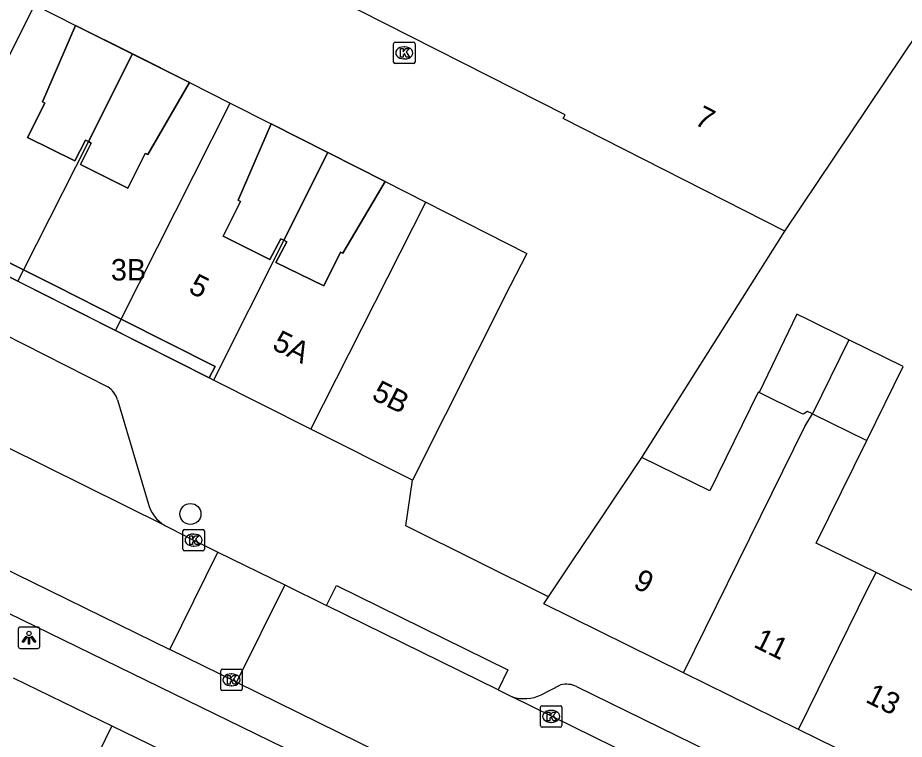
# Model space of a CAD drawing. Extents: x 160356 to 161355, y 381727 to 382845.
# Drawn here: x 160776.6 to 160817.89, y 382478.89 to 382512.49 of the extents above; entities that cross this region are included whole.
import ezdxf

# ---------------------------------------------------------------- set-up
doc = ezdxf.new("R2010")
doc.units = 0
for name, color, linetype in [('IMGEO_Boom', 7, 'Continuous'), ('IMGEO_Kolk', 7, 'Continuous'), ('IMGEO_Lichtpunt', 7, 'Continuous'), ('IMGEO_Pand', 7, 'Continuous'), ('IMGEO_Pand_nummerreeks', 7, 'Continuous'), ('IMGEO_Pand_overbouw', 7, 'Continuous'), ('IMGEO_Rijbaan_lokaal_open', 7, 'Continuous'), ('IMGEO_Voetpad_open', 7, 'Continuous')]:
    doc.layers.add(name, color=color, linetype=linetype)

msp = doc.modelspace()

# ---------------------------------------------------------------- linework, layer by layer
at = {"layer": 'IMGEO_Boom'}
msp.add_circle((160784.641, 382489.379), 0.489, dxfattribs=at)
at = {"layer": 'IMGEO_Kolk'}
for p, q in [((160794.176, 382511.356), (160795.028, 382511.356)), ((160794.101, 382510.43), (160794.101, 382511.282)), ((160794.589, 382511.136), (160794.614, 382511.136)), ((160795.102, 382511.282), (160795.102, 382510.43)), ((160794.612, 382510.576), (160794.587, 382510.576)), ((160795.028, 382510.356), (160794.176, 382510.356)), ((160784.288, 382487.735), (160784.288, 382488.587)), ((160784.363, 382488.661), (160785.215, 382488.661)), ((160785.289, 382488.587), (160785.289, 382487.735)), ((160784.776, 382488.441), (160784.801, 382488.441)), ((160784.799, 382487.881), (160784.774, 382487.881)), ((160785.215, 382487.661), (160784.363, 382487.661)), ((160786.053, 382481.227), (160786.053, 382482.079)), ((160786.128, 382482.153), (160786.98, 382482.153)), ((160787.054, 382482.079), (160787.054, 382481.227)), ((160786.541, 382481.933), (160786.566, 382481.933)), ((160786.98, 382481.153), (160786.128, 382481.153)), ((160786.564, 382481.373), (160786.539, 382481.373)), ((160800.941, 382479.524), (160800.941, 382480.376)), ((160801.016, 382480.45), (160801.868, 382480.45)), ((160801.942, 382480.376), (160801.942, 382479.524)), ((160801.429, 382480.23), (160801.454, 382480.23)), ((160801.452, 382479.67), (160801.427, 382479.67)), ((160801.868, 382479.45), (160801.016, 382479.45))]:
    msp.add_line(p, q, dxfattribs=at)
for points in [[(160794.176, 382511.356), (160795.028, 382511.356)], [(160794.101, 382510.43), (160794.101, 382511.282)], [(160794.422, 382511.056), (160794.545, 382511.056), (160794.545, 382510.905), (160794.675, 382511.056), (160794.839, 382511.056), (160794.693, 382510.905), (160794.846, 382510.656), (160794.694, 382510.656), (160794.609, 382510.82), (160794.545, 382510.753), (160794.545, 382510.656), (160794.422, 382510.656), (160794.422, 382511.056)], [(160795.102, 382511.282), (160795.102, 382510.43)], [(160795.028, 382510.356), (160794.176, 382510.356)], [(160784.288, 382487.735), (160784.288, 382488.587)], [(160784.363, 382488.661), (160785.215, 382488.661)], [(160785.289, 382488.587), (160785.289, 382487.735)], [(160784.609, 382488.361), (160784.732, 382488.361), (160784.732, 382488.21), (160784.862, 382488.361), (160785.026, 382488.361), (160784.88, 382488.21), (160785.033, 382487.961), (160784.881, 382487.961), (160784.796, 382488.125), (160784.732, 382488.058), (160784.732, 382487.961), (160784.609, 382487.961), (160784.609, 382488.361)], [(160785.215, 382487.661), (160784.363, 382487.661)], [(160786.053, 382481.227), (160786.053, 382482.079)], [(160786.128, 382482.153), (160786.98, 382482.153)], [(160787.054, 382482.079), (160787.054, 382481.227)], [(160786.374, 382481.853), (160786.497, 382481.853), (160786.497, 382481.702), (160786.627, 382481.853), (160786.791, 382481.853), (160786.645, 382481.702), (160786.798, 382481.453), (160786.646, 382481.453), (160786.561, 382481.617), (160786.497, 382481.55), (160786.497, 382481.453), (160786.374, 382481.453), (160786.374, 382481.853)], [(160786.98, 382481.153), (160786.128, 382481.153)], [(160800.941, 382479.524), (160800.941, 382480.376)], [(160801.016, 382480.45), (160801.868, 382480.45)], [(160801.942, 382480.376), (160801.942, 382479.524)], [(160801.262, 382480.15), (160801.385, 382480.15), (160801.385, 382479.999), (160801.515, 382480.15), (160801.679, 382480.15), (160801.533, 382479.999), (160801.686, 382479.75), (160801.534, 382479.75), (160801.449, 382479.914), (160801.385, 382479.847), (160801.385, 382479.75), (160801.262, 382479.75), (160801.262, 382480.15)], [(160801.868, 382479.45), (160801.016, 382479.45)]]:
    msp.add_lwpolyline(points, dxfattribs=at)
for centre, start, end in [((160794.178, 382511.28), 91.552, 178.448), ((160794.178, 382511.28), 91.552, 178.448), ((160795.026, 382511.28), 1.552, 88.448), ((160795.026, 382511.28), 1.552, 88.448), ((160794.178, 382510.432), 181.552, 268.448), ((160794.178, 382510.432), 181.552, 268.448), ((160795.026, 382510.432), 271.552, 358.448), ((160795.026, 382510.432), 271.552, 358.448), ((160784.365, 382488.585), 91.552, 178.448), ((160784.365, 382488.585), 91.552, 178.448), ((160785.213, 382488.585), 1.552, 88.448), ((160785.213, 382488.585), 1.552, 88.448), ((160784.365, 382487.737), 181.552, 268.448), ((160784.365, 382487.737), 181.552, 268.448), ((160785.213, 382487.737), 271.552, 358.448), ((160785.213, 382487.737), 271.552, 358.448), ((160786.13, 382482.077), 91.552, 178.448), ((160786.13, 382482.077), 91.552, 178.448), ((160786.978, 382482.077), 1.552, 88.448), ((160786.978, 382482.077), 1.552, 88.448), ((160786.13, 382481.229), 181.552, 268.448), ((160786.13, 382481.229), 181.552, 268.448), ((160786.978, 382481.229), 271.552, 358.448), ((160786.978, 382481.229), 271.552, 358.448), ((160801.018, 382480.374), 91.552, 178.448), ((160801.018, 382480.374), 91.552, 178.448), ((160801.866, 382480.374), 1.552, 88.448), ((160801.866, 382480.374), 1.552, 88.448), ((160801.018, 382479.526), 181.552, 268.448), ((160801.018, 382479.526), 181.552, 268.448), ((160801.866, 382479.526), 271.552, 358.448), ((160801.866, 382479.526), 271.552, 358.448)]:
    msp.add_arc(centre, 0.0765, start, end, dxfattribs=at)
for centre, major_axis, ratio, start_param, end_param in [((160794.588, 382510.856), (-0.387, 0.002), 0.722429, 4.712389, 7.853982), ((160794.613, 382510.856), (-0.39, 0.002), 0.717154, 1.570796, 4.712389), ((160784.775, 382488.161), (-0.387, 0.002), 0.722429, 4.712389, 7.853982), ((160784.8, 382488.161), (-0.39, 0.002), 0.717154, 1.570796, 4.712389), ((160786.54, 382481.653), (-0.387, 0.002), 0.722429, 4.712389, 7.853982), ((160786.565, 382481.653), (-0.39, 0.002), 0.717154, 1.570796, 4.712389), ((160801.428, 382479.95), (-0.387, 0.002), 0.722429, 4.712389, 7.853982), ((160801.453, 382479.95), (-0.39, 0.002), 0.717154, 1.570796, 4.712389)]:
    msp.add_ellipse(centre, major_axis=major_axis, ratio=ratio, start_param=start_param, end_param=end_param, dxfattribs=at)
at = {"layer": 'IMGEO_Lichtpunt'}
for p, q in [((160777.526, 382484.114), (160776.718, 382484.114)), ((160777.526, 382484.114), (160776.718, 382484.114)), ((160776.624, 382484.019), (160776.624, 382483.212)), ((160776.624, 382484.019), (160776.624, 382483.212)), ((160777.62, 382483.212), (160777.62, 382484.019)), ((160777.62, 382483.212), (160777.62, 382484.019)), ((160776.718, 382483.118), (160777.526, 382483.118)), ((160776.718, 382483.118), (160777.526, 382483.118))]:
    msp.add_line(p, q, dxfattribs=at)
for points in [[(160776.998, 382483.683), (160777.037, 382483.655), (160776.849, 382483.393), (160776.811, 382483.42), (160776.998, 382483.683)], [(160777.1, 382483.635), (160777.147, 382483.635), (160777.147, 382483.313), (160777.1, 382483.313), (160777.1, 382483.635)], [(160777.21, 382483.655), (160777.248, 382483.682), (160777.435, 382483.42), (160777.396, 382483.392), (160777.21, 382483.655)]]:
    msp.add_lwpolyline(points, dxfattribs=at)
msp.add_circle((160777.123, 382483.817), 0.0994, dxfattribs=at)
for centre, start, end in [((160776.718, 382484.019), 90, 180), ((160776.718, 382484.019), 90, 180), ((160777.526, 382484.019), 0, 90), ((160777.526, 382484.019), 0, 90), ((160776.718, 382483.212), 180, 270), ((160776.718, 382483.212), 180, 270), ((160777.526, 382483.212), 270, 0), ((160777.526, 382483.212), 270, 360)]:
    msp.add_arc(centre, 0.0946, start, end, dxfattribs=at)
at = {"layer": 'IMGEO_Pand'}
for points in [[(160812.331, 382502.558), (160820.876, 382515.321), (160798.417, 382527.033), (160799.163, 382528.464), (160793.416, 382531.651)], [(160812.331, 382502.558), (160802.004, 382507.798), (160802.09, 382507.968), (160791.3, 382513.443), (160794.82, 382520.017), (160794.601, 382520.138), (160795.088, 382521.018), (160784.777, 382526.556), (160784.711, 382526.444), (160784.461, 382526.591)], [(160772.322, 382503.039), (160777.393, 382513.097)], [(160777.393, 382513.097), (160779.292, 382512.135)], [(160779.887, 382506.727), (160779.753, 382506.797), (160779.251, 382505.823), (160777.057, 382506.918), (160777.86, 382508.514), (160777.749, 382508.58), (160779.292, 382512.135)], [(160784.593, 382509.477), (160782.656, 382506.125), (160782.534, 382506.17), (160781.729, 382504.559), (160779.528, 382505.659), (160780.021, 382506.658), (160779.887, 382506.727)], [(160784.593, 382509.477), (160786.493, 382508.512)], [(160781.422, 382498.451), (160786.493, 382508.512)], [(160786.493, 382508.512), (160788.394, 382507.546)], [(160788.991, 382502.131), (160788.856, 382502.201), (160788.343, 382501.233), (160786.164, 382502.326), (160786.975, 382503.929), (160786.859, 382503.991), (160788.394, 382507.546)], [(160779.887, 382506.727), (160776.871, 382500.745)], [(160793.704, 382504.866), (160791.741, 382501.533), (160791.631, 382501.578), (160790.846, 382500), (160788.623, 382501.087), (160789.126, 382502.062), (160788.991, 382502.131)], [(160793.704, 382504.866), (160795.61, 382503.899)], [(160790.249, 382493.331), (160795.61, 382503.899)], [(160795.61, 382503.899), (160800.303, 382501.518), (160799.539, 382500), (160794.983, 382490.948)], [(160772.322, 382503.039), (160776.871, 382500.745)], [(160788.991, 382502.131), (160785.711, 382495.616)], [(160776.871, 382500.745), (160778.35, 382500), (160781.422, 382498.451)], [(160815.3, 382497.497), (160813.329, 382498.468), (160812.978, 382498.64), (160812.88, 382498.688), (160811.124, 382495.03)], [(160781.422, 382498.451), (160785.79, 382496.249), (160785.515, 382495.715)], [(160815.3, 382497.497), (160813.614, 382494.038)], [(160816.136, 382492.795), (160817.836, 382496.247), (160815.3, 382497.497)], [(160785.711, 382495.616), (160785.515, 382495.715)], [(160790.249, 382493.331), (160785.711, 382495.616)], [(160811.124, 382495.03), (160811.087, 382495.048), (160808.826, 382490.459), (160805.669, 382492.014)], [(160813.614, 382494.038), (160813.372, 382494.157), (160813.256, 382494.079), (160813.17, 382494.022), (160813.095, 382494.059), (160811.124, 382495.03)], [(160807.606, 382481.982), (160813.255, 382493.456), (160813.614, 382494.038)], [(160813.614, 382494.038), (160816.136, 382492.795)], [(160794.983, 382490.948), (160790.249, 382493.331)], [(160816.574, 382486.646), (160813.784, 382488.02), (160816.136, 382492.795)], [(160801.311, 382485.518), (160802.411, 382487.157), (160803.878, 382489.344), (160805.669, 382492.014)], [(160824.368, 382489.208), (160821.64, 382490.552), (160819.102, 382485.4), (160816.574, 382486.646)], [(160812.958, 382479.345), (160816.223, 382485.975), (160816.574, 382486.646)], [(160807.606, 382481.982), (160801.092, 382485.191), (160801.311, 382485.518)], [(160812.958, 382479.345), (160807.606, 382481.982)], [(160776.391, 382481.754), (160780.981, 382479.514)], [(160780.981, 382479.514), (160777.31, 382471.991)], [(160780.981, 382479.514), (160785.607, 382477.257)], [(160818.233, 382476.747), (160812.958, 382479.345)]]:
    msp.add_lwpolyline(points, dxfattribs=at)
at = {"layer": 'IMGEO_Pand_overbouw'}
for points in [[(160779.887, 382506.727), (160781.943, 382510.806), (160779.292, 382512.135), (160777.749, 382508.58), (160777.86, 382508.514), (160777.057, 382506.918), (160779.251, 382505.823), (160779.753, 382506.797)], [(160779.887, 382506.727), (160780.021, 382506.658), (160779.528, 382505.659), (160781.729, 382504.559), (160782.534, 382506.17), (160782.656, 382506.125), (160784.593, 382509.477), (160781.943, 382510.806)], [(160788.394, 382507.546), (160786.859, 382503.991), (160786.975, 382503.929), (160786.164, 382502.326), (160788.343, 382501.233), (160788.856, 382502.201), (160788.991, 382502.131), (160791.044, 382506.209)], [(160793.704, 382504.866), (160791.044, 382506.209), (160788.991, 382502.131), (160789.126, 382502.062), (160788.623, 382501.087), (160790.846, 382500), (160791.631, 382501.578), (160791.741, 382501.533)], [(160772.322, 382503.039), (160772.057, 382502.513), (160776.604, 382500.216), (160776.871, 382500.745)], [(160781.422, 382498.451), (160778.35, 382500), (160776.871, 382500.745), (160776.604, 382500.216), (160781.153, 382497.918)], [(160785.515, 382495.715), (160785.79, 382496.249), (160781.422, 382498.451), (160781.153, 382497.918)]]:
    msp.add_lwpolyline(points, close=True, dxfattribs=at)
at = {"layer": 'IMGEO_Rijbaan_lokaal_open'}
for points in [[(160779.292, 382512.135), (160784.593, 382509.477)], [(160788.394, 382507.546), (160793.704, 382504.866)], [(160805.669, 382492.014), (160812.331, 382502.558)], [(160783.449, 382488.843), (160772.35, 382494.335), (160768.211, 382496.514), (160762.886, 382499.967)], [(160766.19, 382491.635), (160783.682, 382483.063)], [(160801.311, 382485.518), (160794.669, 382488.822), (160794.983, 382490.948)], [(160783.449, 382488.843), (160783.699, 382488.719), (160784.789, 382488.161), (160785.477, 382487.822), (160785.92, 382487.604)], [(160783.682, 382483.063), (160785.92, 382487.604)], [(160785.92, 382487.604), (160789.03, 382486.075)], [(160789.03, 382486.075), (160786.792, 382481.538)], [(160789.03, 382486.075), (160790.975, 382485.118)], [(160798.965, 382481.189), (160790.975, 382485.118)], [(160786.792, 382481.538), (160783.682, 382483.063)], [(160786.792, 382481.538), (160793.451, 382478.275), (160814.21, 382468.085)], [(160798.965, 382481.189), (160799.626, 382480.864)], [(160839.679, 382461.164), (160799.626, 382480.864)]]:
    msp.add_lwpolyline(points, dxfattribs=at)
at = {"layer": 'IMGEO_Voetpad_open'}
for points in [[(160785.515, 382495.715), (160758.228, 382509.498)], [(160765.616, 382503.032), (160771.543, 382500), (160774.903, 382498.281), (160780.793, 382495.301)], [(160781.249, 382494.69), (160782.673, 382489.887)], [(160810.987, 382467.666), (160792.652, 382476.697), (160793.057, 382477.583), (160791.991, 382478.104), (160791.553, 382477.241), (160767.171, 382489.145)], [(160790.975, 382485.118), (160791.442, 382486.048), (160799.424, 382482.122), (160798.965, 382481.189)], [(160800.979, 382480.959), (160801.882, 382481.417)], [(160802.625, 382481.346), (160811.136, 382477.167), (160810.662, 382476.305), (160811.72, 382475.748), (160812.178, 382476.666), (160821.736, 382471.957)]]:
    msp.add_lwpolyline(points, dxfattribs=at)
for centre, radius, start, end in [((160780.127, 382494.328), 1.179, 17.8708, 55.5985), ((160784.321, 382490.301), 1.699, 194.1184, 239.1281), ((160802.151, 382480.308), 1.141, 65.4552, 103.6278), ((160800.183, 382482.613), 1.836, 252.3381, 295.6947)]:
    msp.add_arc(centre, radius, start, end, dxfattribs=at)

# ---------------------------------------------------------------- texts
at = {"layer": 'IMGEO_Pand_nummerreeks'}
for s, rotation, p in [('7', 333.0939, (160808.062, 382507.55)), ('5', 333.2443, (160784.498, 382499.723)), ('5A', 333.2754, (160788.394, 382497.087)), ('5B', 333.2754, (160793.031, 382494.752)), ('9', 333.7757, (160805.215, 382485.969)), ('11', 333.7787, (160810.819, 382483.208)), ('13', 333.7787, (160816.03, 382480.642))]:
    msp.add_text(s, height=1, rotation=rotation, dxfattribs=at).set_placement(p)
msp.add_text('3B', height=1, dxfattribs=at).set_placement((160780.937, 382500.254))

doc.saveas('drawing.dxf')
